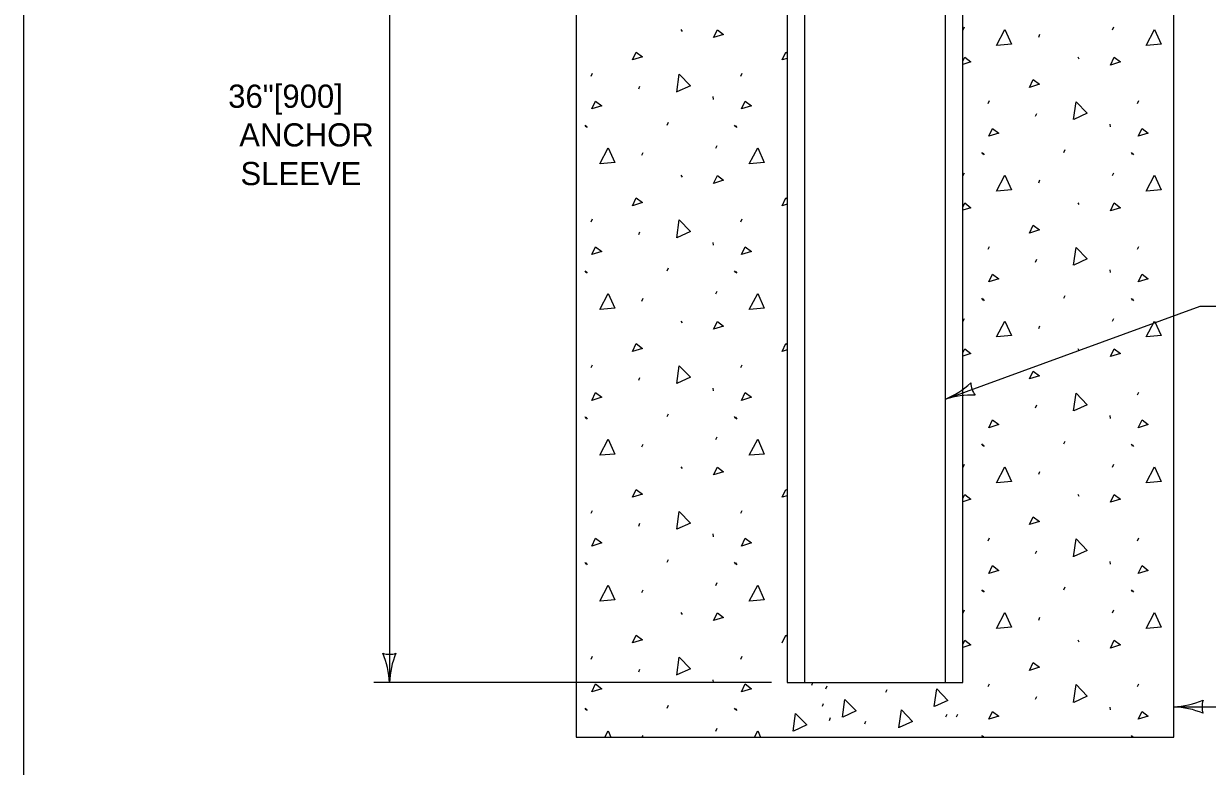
# Model space of a CAD drawing. Extents: x 49940 to 50043, y 49986 to 50011.
# Drawn here: x 49999.384 to 50002.443, y 49992.555 to 49994.476 of the extents above; entities that cross this region are included whole.
import ezdxf

# ---------------------------------------------------------------- set-up
doc = ezdxf.new("R2010")
doc.units = 0
for name, color, linetype in [('Level 1', 7, 'Continuous'), ('Level 2', 7, 'Continuous'), ('Level 3', 7, 'Continuous'), ('Level 4', 7, 'Continuous')]:
    doc.layers.add(name, color=color, linetype=linetype)

msp = doc.modelspace()

# ---------------------------------------------------------------- linework, layer by layer
at = {"layer": 'Level 1'}
for p, q in [((50000.8115, 49995.3566), (50000.8115, 49992.6303)), ((50002.3564, 49992.6303), (50002.3564, 49995.3566)), ((50001.0825, 49994.4605), (50001.0857, 49994.4556)), ((50001.8123, 49994.4597), (50001.8153, 49994.467)), ((50002.1986, 49994.4597), (50002.2019, 49994.467)), ((50002.0075, 49994.4411), (50002.0106, 49994.4484)), ((50002.1084, 49994.3896), (50002.1115, 49994.3846)), ((50000.8508, 49994.3402), (50000.854, 49994.3474)), ((50001.2373, 49994.3402), (50001.2406, 49994.3474)), ((50000.9735, 49994.307), (50000.9766, 49994.3143)), ((50001.1653, 49994.2869), (50001.166, 49994.2795)), ((50001.8768, 49994.2693), (50001.88, 49994.2766)), ((50002.2633, 49994.2693), (50002.2666, 49994.2766)), ((50001.9994, 49994.2362), (50002.0025, 49994.2435)), ((50000.8338, 49994.2134), (50000.8371, 49994.2087)), ((50000.8371, 49994.2116), (50000.8404, 49994.2068)), ((50001.0468, 49994.2134), (50001.0501, 49994.2207)), ((50001.2203, 49994.2134), (50001.2237, 49994.2087)), ((50001.2237, 49994.2116), (50001.2269, 49994.2068)), ((50002.1913, 49994.2159), (50002.192, 49994.2087)), ((50001.1727, 49994.1537), (50001.176, 49994.1609)), ((50002.0728, 49994.1426), (50002.0761, 49994.15)), ((50000.9815, 49994.1351), (50000.9848, 49994.1423)), ((50001.8598, 49994.1426), (50001.863, 49994.1378)), ((50001.863, 49994.1408), (50001.8662, 49994.136)), ((50002.2463, 49994.1426), (50002.2495, 49994.1378)), ((50002.2495, 49994.1408), (50002.2528, 49994.136)), ((50001.0825, 49994.0835), (50001.0857, 49994.0785)), ((50001.8123, 49994.0828), (50001.8153, 49994.09)), ((50002.1986, 49994.0828), (50002.2019, 49994.09)), ((50002.0075, 49994.0642), (50002.0106, 49994.0715)), ((50002.1084, 49994.0126), (50002.1115, 49994.0077)), ((50000.8508, 49993.9632), (50000.854, 49993.9705)), ((50001.2373, 49993.9632), (50001.2406, 49993.9705)), ((50000.9735, 49993.9301), (50000.9766, 49993.9374)), ((50001.1653, 49993.9099), (50001.166, 49993.9026)), ((50001.8768, 49993.8922), (50001.88, 49993.8996)), ((50002.2633, 49993.8922), (50002.2666, 49993.8996)), ((50001.0468, 49993.8366), (50001.0501, 49993.8438)), ((50001.9994, 49993.8592), (50002.0025, 49993.8665)), ((50002.1913, 49993.839), (50002.192, 49993.8318)), ((50000.8338, 49993.8366), (50000.8371, 49993.8318)), ((50000.8371, 49993.8347), (50000.8404, 49993.83)), ((50001.2203, 49993.8366), (50001.2237, 49993.8318)), ((50001.2237, 49993.8347), (50001.2269, 49993.83)), ((50001.1727, 49993.7767), (50001.176, 49993.784)), ((50000.9815, 49993.7582), (50000.9848, 49993.7654)), ((50001.8598, 49993.7656), (50001.863, 49993.7606)), ((50001.863, 49993.7638), (50001.8662, 49993.7589)), ((50002.0728, 49993.7656), (50002.0761, 49993.7729)), ((50002.2463, 49993.7656), (50002.2495, 49993.7606)), ((50002.2495, 49993.7638), (50002.2528, 49993.7589)), ((50001.0825, 49993.7066), (50001.0857, 49993.7017)), ((50001.8123, 49993.7058), (50001.8153, 49993.713)), ((50002.0075, 49993.6872), (50002.0106, 49993.6945)), ((50002.1986, 49993.7058), (50002.2019, 49993.713)), ((50002.1084, 49993.6355), (50002.1115, 49993.6307)), ((50000.8508, 49993.5861), (50000.854, 49993.5935)), ((50001.2373, 49993.5861), (50001.2406, 49993.5935)), ((50000.9735, 49993.5532), (50000.9766, 49993.5605)), ((50001.1653, 49993.5329), (50001.166, 49993.5258)), ((50002.2633, 49993.5154), (50002.2666, 49993.5226)), ((50001.9994, 49993.4823), (50002.0025, 49993.4897)), ((50000.8338, 49993.4595), (50000.8371, 49993.4547)), ((50000.8371, 49993.4577), (50000.8404, 49993.4528)), ((50001.0468, 49993.4595), (50001.0501, 49993.4668)), ((50001.2203, 49993.4595), (50001.2237, 49993.4547)), ((50001.2237, 49993.4577), (50001.2269, 49993.4528)), ((50002.1913, 49993.462), (50002.192, 49993.4547)), ((50000.9815, 49993.3811), (50000.9848, 49993.3884)), ((50001.1727, 49993.3998), (50001.176, 49993.407)), ((50001.8598, 49993.3888), (50001.863, 49993.3837)), ((50001.863, 49993.3867), (50001.8662, 49993.3819)), ((50002.0728, 49993.3888), (50002.0761, 49993.396)), ((50002.2463, 49993.3888), (50002.2495, 49993.3837)), ((50002.2495, 49993.3867), (50002.2528, 49993.3819)), ((50001.0825, 49993.3296), (50001.0857, 49993.3247)), ((50001.8123, 49993.3288), (50001.8153, 49993.3361)), ((50002.0075, 49993.3103), (50002.0106, 49993.3175)), ((50002.1986, 49993.3288), (50002.2019, 49993.3361)), ((50002.1084, 49993.2585), (50002.1115, 49993.2538)), ((50000.8508, 49993.2093), (50000.854, 49993.2166)), ((50001.2373, 49993.2093), (50001.2406, 49993.2166)), ((50000.9735, 49993.1762), (50000.9766, 49993.1835)), ((50001.1653, 49993.1559), (50001.166, 49993.1486)), ((50001.8768, 49993.1384), (50001.88, 49993.1457)), ((50002.2633, 49993.1384), (50002.2666, 49993.1457)), ((50001.9994, 49993.1054), (50002.0025, 49993.1126)), ((50000.8338, 49993.0826), (50000.8371, 49993.0778)), ((50000.8371, 49993.0808), (50000.8404, 49993.0758)), ((50001.0468, 49993.0826), (50001.0501, 49993.0899)), ((50001.2203, 49993.0826), (50001.2237, 49993.0778)), ((50001.2237, 49993.0808), (50001.2269, 49993.0758)), ((50002.1913, 49993.0849), (50002.192, 49993.0779)), ((50000.9815, 49993.0042), (50000.9848, 49993.0115)), ((50001.1727, 49993.0227), (50001.176, 49993.03)), ((50001.8598, 49993.0117), (50001.863, 49993.0068)), ((50002.0728, 49993.0117), (50002.0761, 49993.019)), ((50002.2463, 49993.0117), (50002.2495, 49993.0068)), ((50001.863, 49993.0099), (50001.8662, 49993.0049)), ((50002.2495, 49993.0099), (50002.2528, 49993.0049)), ((50001.0825, 49992.9526), (50001.0857, 49992.9478)), ((50001.8123, 49992.9517), (50001.8153, 49992.9592)), ((50002.1986, 49992.9517), (50002.2019, 49992.9592)), ((50002.0075, 49992.9333), (50002.0106, 49992.9405)), ((50002.1084, 49992.8817), (50002.1115, 49992.8768)), ((50000.8508, 49992.8323), (50000.854, 49992.8395)), ((50001.2373, 49992.8323), (50001.2406, 49992.8395)), ((50000.9735, 49992.7993), (50000.9766, 49992.8065)), ((50001.1653, 49992.7789), (50001.166, 49992.7717)), ((50001.3568, 49992.7713), (50001.8111, 49992.7713)), ((50001.4208, 49992.7647), (50001.4239, 49992.7718)), ((50001.8768, 49992.7614), (50001.88, 49992.7686)), ((50002.2633, 49992.7614), (50002.2666, 49992.7686)), ((50001.4572, 49992.7555), (50001.4605, 49992.7627)), ((50001.6122, 49992.7464), (50001.6154, 49992.7536)), ((50000.8338, 49992.7056), (50000.8371, 49992.7008)), ((50001.0468, 49992.7056), (50001.0501, 49992.7129)), ((50001.2203, 49992.7056), (50001.2237, 49992.7008)), ((50001.4482, 49992.7101), (50001.4514, 49992.7173)), ((50001.9994, 49992.7284), (50002.0025, 49992.7356)), ((50002.1913, 49992.708), (50002.192, 49992.7008)), ((50000.8371, 49992.7038), (50000.8404, 49992.6989)), ((50001.2237, 49992.7038), (50001.2269, 49992.6989)), ((50001.4664, 49992.6737), (50001.4696, 49992.6809)), ((50001.7675, 49992.6829), (50001.7706, 49992.69)), ((50001.7947, 49992.6829), (50001.798, 49992.69)), ((50001.1727, 49992.6457), (50001.176, 49992.6532)), ((50001.5576, 49992.6646), (50001.5608, 49992.6719)), ((50000.8115, 49992.6303), (50002.3564, 49992.6303)), ((50000.9828, 49992.6303), (50000.9848, 49992.6346)), ((50001.8598, 49992.6348), (50001.8628, 49992.6303)), ((50001.863, 49992.633), (50001.8647, 49992.6303)), ((50002.2463, 49992.6348), (50002.2493, 49992.6303)), ((50002.2495, 49992.633), (50002.2512, 49992.6303))]:
    msp.add_line(p, q, dxfattribs=at)
msp.add_lwpolyline([(49999.3835, 49998.9992), (50016.7501, 49998.9992), (50016.7501, 49987.7988), (49999.3835, 49987.7988)], close=True, dxfattribs=at)
for points in [[(50001.8111, 49992.7713), (50001.8111, 49995.6046), (50001.3568, 49995.6046), (50001.3568, 49992.7713)], [(50001.1671, 49994.4394), (50001.1768, 49994.4597), (50001.1929, 49994.4477), (50001.1671, 49994.4394)], [(50001.8985, 49994.4193), (50001.9203, 49994.4607), (50001.9372, 49994.4226), (50001.8992, 49994.4193)], [(50002.2851, 49994.4193), (50002.3069, 49994.4607), (50002.3238, 49994.4226), (50002.2859, 49994.4193)], [(50000.9574, 49994.3817), (50000.9672, 49994.402), (50000.9833, 49994.3898), (50000.9574, 49994.3817)], [(50001.3441, 49994.3817), (50001.3537, 49994.402), (50001.3568, 49994.3997)], [(50001.8111, 49994.3784), (50001.8161, 49994.3888), (50001.8323, 49994.3766), (50001.8111, 49994.37)], [(50002.1931, 49994.3685), (50002.2027, 49994.3888), (50002.2189, 49994.3766), (50002.1931, 49994.3685)], [(50001.3568, 49994.3858), (50001.3441, 49994.3817)], [(50001.0716, 49994.2988), (50001.0781, 49994.3448), (50001.1069, 49994.315), (50001.0724, 49994.299)], [(50001.9834, 49994.3109), (50001.9931, 49994.3312), (50002.0092, 49994.3189), (50001.9834, 49994.3109)], [(50000.8524, 49994.2554), (50000.8621, 49994.2755), (50000.8782, 49994.2635), (50000.8524, 49994.2554)], [(50001.239, 49994.2554), (50001.2488, 49994.2755), (50001.2647, 49994.2635), (50001.239, 49994.2554)], [(50002.0976, 49994.2278), (50002.104, 49994.2738), (50002.1329, 49994.2441), (50002.0985, 49994.2281)], [(50001.8783, 49994.1845), (50001.8879, 49994.2047), (50001.9042, 49994.1926), (50001.8783, 49994.1845)], [(50002.2649, 49994.1845), (50002.2746, 49994.2047), (50002.2907, 49994.1926), (50002.2649, 49994.1845)], [(50000.8727, 49994.1134), (50000.8944, 49994.1545), (50000.9114, 49994.1166), (50000.8734, 49994.1134)], [(50001.2591, 49994.1134), (50001.281, 49994.1545), (50001.2978, 49994.1166), (50001.2599, 49994.1134)], [(50001.1671, 49994.0624), (50001.1768, 49994.0827), (50001.1929, 49994.0706), (50001.1671, 49994.0624)], [(50001.8985, 49994.0424), (50001.9203, 49994.0836), (50001.9372, 49994.0457), (50001.8992, 49994.0424)], [(50002.2851, 49994.0424), (50002.3069, 49994.0836), (50002.3238, 49994.0457), (50002.2859, 49994.0424)], [(50000.9574, 49994.0048), (50000.9672, 49994.025), (50000.9833, 49994.0129), (50000.9574, 49994.0048)], [(50001.3441, 49994.0048), (50001.3537, 49994.025), (50001.3568, 49994.0226)], [(50001.3568, 49994.0088), (50001.3441, 49994.0048)], [(50001.8111, 49994.0014), (50001.8161, 49994.0118), (50001.8323, 49993.9996), (50001.8111, 49993.993)], [(50002.1931, 49993.9916), (50002.2027, 49994.0118), (50002.2189, 49993.9996), (50002.1931, 49993.9916)], [(50001.0716, 49993.9218), (50001.0781, 49993.9679), (50001.1069, 49993.9381), (50001.0724, 49993.9221)], [(50001.9834, 49993.9339), (50001.9931, 49993.9541), (50002.0092, 49993.942), (50001.9834, 49993.9339)], [(50000.8524, 49993.8785), (50000.8621, 49993.8986), (50000.8782, 49993.8867), (50000.8524, 49993.8785)], [(50001.239, 49993.8785), (50001.2488, 49993.8986), (50001.2647, 49993.8867), (50001.239, 49993.8785)], [(50002.0976, 49993.8509), (50002.104, 49993.8971), (50002.1329, 49993.8673), (50002.0985, 49993.8512)], [(50001.8783, 49993.8076), (50001.8879, 49993.8278), (50001.9042, 49993.8156), (50001.8783, 49993.8076)], [(50002.2649, 49993.8076), (50002.2746, 49993.8278), (50002.2907, 49993.8156), (50002.2649, 49993.8076)], [(50000.8727, 49993.7364), (50000.8944, 49993.7775), (50000.9114, 49993.7397), (50000.8734, 49993.7364)], [(50001.2591, 49993.7364), (50001.281, 49993.7775), (50001.2978, 49993.7397), (50001.2599, 49993.7364)], [(50001.1671, 49993.6854), (50001.1768, 49993.7057), (50001.1929, 49993.6936), (50001.1671, 49993.6854)], [(50001.8985, 49993.6654), (50001.9203, 49993.7066), (50001.9372, 49993.6687), (50001.8992, 49993.6654)], [(50002.2851, 49993.6654), (50002.3069, 49993.7066), (50002.3238, 49993.6687), (50002.2859, 49993.6654)], [(50000.9574, 49993.6278), (50000.9672, 49993.648), (50000.9833, 49993.6359), (50000.9574, 49993.6278)], [(50001.3441, 49993.6278), (50001.3537, 49993.648), (50001.3568, 49993.6457)], [(50001.3568, 49993.6319), (50001.3441, 49993.6278)], [(50001.8111, 49993.6243), (50001.8161, 49993.6348), (50001.8323, 49993.6227), (50001.8111, 49993.616)], [(50002.1931, 49993.6146), (50002.2027, 49993.6348), (50002.2189, 49993.6227), (50002.1931, 49993.6146)], [(50001.0716, 49993.5449), (50001.0781, 49993.591), (50001.1069, 49993.5611), (50001.0724, 49993.5451)], [(50001.9834, 49993.557), (50001.9931, 49993.5771), (50002.0092, 49993.5651), (50001.9834, 49993.557)], [(50000.8524, 49993.5014), (50000.8621, 49993.5217), (50000.8782, 49993.5096), (50000.8524, 49993.5014)], [(50001.239, 49993.5014), (50001.2488, 49993.5217), (50001.2647, 49993.5096), (50001.239, 49993.5014)], [(50002.0976, 49993.474), (50002.104, 49993.5201), (50002.1329, 49993.4902), (50002.0985, 49993.4742)], [(50001.8783, 49993.4306), (50001.8879, 49993.4508), (50001.9042, 49993.4387), (50001.8783, 49993.4306)], [(50002.2649, 49993.4306), (50002.2746, 49993.4508), (50002.2907, 49993.4387), (50002.2649, 49993.4306)], [(50000.8727, 49993.3594), (50000.8944, 49993.4006), (50000.9114, 49993.3626), (50000.8734, 49993.3594)], [(50001.2591, 49993.3594), (50001.281, 49993.4006), (50001.2978, 49993.3626), (50001.2599, 49993.3594)], [(50001.1671, 49993.3086), (50001.1768, 49993.3288), (50001.1929, 49993.3167), (50001.1671, 49993.3086)], [(50001.8985, 49993.2884), (50001.9203, 49993.3296), (50001.9372, 49993.2918), (50001.8992, 49993.2884)], [(50002.2851, 49993.2884), (50002.3069, 49993.3296), (50002.3238, 49993.2918), (50002.2859, 49993.2884)], [(50000.9574, 49993.2509), (50000.9672, 49993.271), (50000.9833, 49993.259), (50000.9574, 49993.2509)], [(50001.3441, 49993.2509), (50001.3537, 49993.271), (50001.3568, 49993.2688)], [(50001.8111, 49993.2474), (50001.8161, 49993.2578), (50001.8323, 49993.2457), (50001.8111, 49993.2391)], [(50002.1931, 49993.2377), (50002.2027, 49993.2578), (50002.2189, 49993.2457), (50002.1931, 49993.2377)], [(50001.3568, 49993.2548), (50001.3441, 49993.2509)], [(50001.0716, 49993.1679), (50001.0781, 49993.2141), (50001.1069, 49993.1841), (50001.0724, 49993.1682)], [(50001.9834, 49993.18), (50001.9931, 49993.2002), (50002.0092, 49993.188), (50001.9834, 49993.18)], [(50000.8524, 49993.1245), (50000.8621, 49993.1448), (50000.8782, 49993.1326), (50000.8524, 49993.1245)], [(50001.239, 49993.1245), (50001.2488, 49993.1448), (50001.2647, 49993.1326), (50001.239, 49993.1245)], [(50002.0976, 49993.097), (50002.104, 49993.143), (50002.1329, 49993.1132), (50002.0985, 49993.0973)], [(50001.8783, 49993.0536), (50001.8879, 49993.0739), (50001.9042, 49993.0617), (50001.8783, 49993.0536)], [(50002.2649, 49993.0536), (50002.2746, 49993.0739), (50002.2907, 49993.0617), (50002.2649, 49993.0536)], [(50000.8727, 49992.9824), (50000.8944, 49993.0235), (50000.9114, 49992.9857), (50000.8734, 49992.9824)], [(50001.2591, 49992.9824), (50001.281, 49993.0235), (50001.2978, 49992.9857), (50001.2599, 49992.9824)], [(50001.1671, 49992.9317), (50001.1768, 49992.9517), (50001.1929, 49992.9396), (50001.1671, 49992.9317)], [(50001.8985, 49992.9116), (50001.9203, 49992.9526), (50001.9372, 49992.9148), (50001.8992, 49992.9116)], [(50002.2851, 49992.9116), (50002.3069, 49992.9526), (50002.3238, 49992.9148), (50002.2859, 49992.9116)], [(50000.9574, 49992.8739), (50000.9672, 49992.894), (50000.9833, 49992.8819), (50000.9574, 49992.8739)], [(50001.3441, 49992.8739), (50001.3537, 49992.894), (50001.3568, 49992.8917)], [(50001.8111, 49992.8703), (50001.8161, 49992.8809), (50001.8323, 49992.8688), (50001.8111, 49992.8622)], [(50002.1931, 49992.8607), (50002.2027, 49992.8809), (50002.2189, 49992.8688), (50002.1931, 49992.8607)], [(50001.0716, 49992.7909), (50001.0781, 49992.837), (50001.1069, 49992.8071), (50001.0724, 49992.7911)], [(50001.9834, 49992.803), (50001.9931, 49992.8232), (50002.0092, 49992.8111), (50001.9834, 49992.803)], [(50000.8524, 49992.7476), (50000.8621, 49992.7678), (50000.8782, 49992.7557), (50000.8524, 49992.7476)], [(50001.239, 49992.7476), (50001.2488, 49992.7678), (50001.2647, 49992.7557), (50001.239, 49992.7476)], [(50001.7374, 49992.7092), (50001.7437, 49992.7553), (50001.7727, 49992.7255), (50001.7382, 49992.7094)], [(50002.0976, 49992.72), (50002.104, 49992.7662), (50002.1329, 49992.7363), (50002.0985, 49992.7203)], [(50001.5002, 49992.6818), (50001.5066, 49992.728), (50001.5355, 49992.6982), (50001.501, 49992.6822)], [(50001.3725, 49992.6455), (50001.379, 49992.6916), (50001.4078, 49992.6618), (50001.3734, 49992.6457)], [(50001.6461, 49992.6546), (50001.6526, 49992.7007), (50001.6815, 49992.6709), (50001.6469, 49992.6549)], [(50001.8783, 49992.6768), (50001.8879, 49992.6968), (50001.9042, 49992.6847), (50001.8783, 49992.6768)], [(50002.2649, 49992.6768), (50002.2746, 49992.6968), (50002.2907, 49992.6847), (50002.2649, 49992.6768)], [(50000.8858, 49992.6303), (50000.8944, 49992.6466), (50000.9017, 49992.6303)], [(50001.2724, 49992.6303), (50001.281, 49992.6466), (50001.2882, 49992.6303)]]:
    msp.add_lwpolyline(points, dxfattribs=at)
at = {"layer": 'Level 3'}
for p, q in [((50000.3291, 49995.6046), (50000.3291, 49992.7713)), ((50001.7662, 49993.5045), (50002.4245, 49993.7454)), ((50002.4245, 49993.7454), (50002.6177, 49993.7454)), ((50001.3168, 49992.7713), (50000.2891, 49992.7713)), ((50002.3564, 49992.7088), (50002.6055, 49992.7088))]:
    msp.add_line(p, q, dxfattribs=at)
for centre, radius, start, end in [((50001.6754, 49993.7191), 0.233, 292.9233, 312.1731), ((50001.8866, 49993.5486), 0.0548, 182.2348, 217.9572), ((50001.8339, 49993.2928), 0.2223, 87.552, 107.7355), ((50000.3291, 49992.8995), 0.0548, 252.1388, 287.8612), ((50000.0964, 49992.7598), 0.233, 2.8273, 22.0772), ((50000.5512, 49992.7622), 0.2223, 157.456, 177.6395), ((50002.3449, 49992.9415), 0.233, 272.8273, 292.0772), ((50002.3472, 49992.4867), 0.2223, 67.456, 87.6395), ((50002.4846, 49992.7088), 0.0548, 162.1388, 197.8612)]:
    msp.add_arc(centre, radius, start, end, dxfattribs=at)
at = {"layer": 'Level 4'}
for p, q in [((50001.4029, 49992.7713), (50001.4029, 49995.6046)), ((50001.7662, 49992.7713), (50001.7662, 49995.6046))]:
    msp.add_line(p, q, dxfattribs=at)

# ---------------------------------------------------------------- texts
at = {"layer": 'Level 2'}
for s, p in [('36"[900]', (49999.9123, 49994.258)), ('ANCHOR', (49999.9408, 49994.158)), ('SLEEVE', (49999.944, 49994.058))]:
    msp.add_text(s, height=0.06, dxfattribs=at).set_placement(p)

doc.saveas('drawing.dxf')
